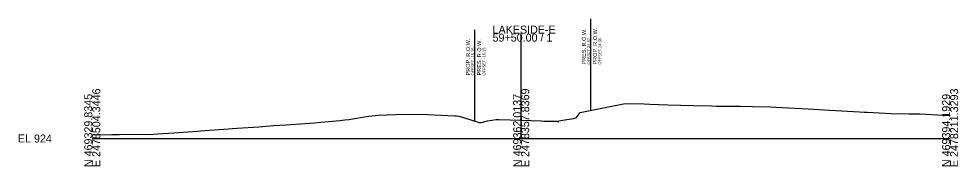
# Model space of a CAD drawing. Extents: x -26 to 2478923, y -10 to 469990.
# Drawn here: x -25.7 to 302.8, y 9990.3 to 10041.9 of the extents above; entities that cross this region are included whole.
import ezdxf

# ---------------------------------------------------------------- set-up
doc = ezdxf.new("R2010")
doc.units = 0
for name, color, linetype in [('DESIGN - ROW - Right-of-Way and Easement Labels', 7, 'Continuous'), ('DESIGN - ROW - Right-of-Way Linework', 7, 'Continuous'), ('DESIGN - SHEET - Light Grid', 7, 'Continuous'), ('SURVEY - GROUND - Top of Ground', 7, 'Continuous'), ('SURVEY - PROPERTY - ROW Lines', 7, 'Continuous'), ('SURVEY - PROPERTY - ROW Lines Text', 7, 'Continuous')]:
    doc.layers.add(name, color=color, linetype=linetype)

msp = doc.modelspace()

# ---------------------------------------------------------------- linework, layer by layer
at = {"layer": 'DESIGN - ROW - Right-of-Way Linework'}
for p, q in [((174.36, 10009.86), (174.36, 10041.86)), ((133.85, 10006.05), (133.85, 10038.05))]:
    msp.add_line(p, q, dxfattribs=at)
at = {"layer": 'DESIGN - SHEET - Light Grid'}
for p, q in [((150, 10000), (150, 10036.68)), ((0, 10000), (150, 10000)), ((150, 10000), (300, 10000))]:
    msp.add_line(p, q, dxfattribs=at)
at = {"layer": 'SURVEY - GROUND - Top of Ground'}
msp.add_lwpolyline([(0, 10001.32), (6.85, 10001.39), (9.58, 10001.4), (15.41, 10001.49), (19.85, 10001.43), (22.87, 10001.61), (28.58, 10001.93), (36.78, 10002.58), (37.8, 10002.67), (47.67, 10003.42), (48.91, 10003.53), (50.72, 10003.67), (58.29, 10004.06), (63.43, 10004.52), (67.82, 10004.76), (74.45, 10005.28), (77.75, 10005.49), (79.88, 10005.69), (86.74, 10006.31), (88.29, 10006.49), (89.73, 10006.67), (96.58, 10007.82), (100.11, 10008.13), (106.13, 10008.38), (110.39, 10008.49), (117.26, 10008.34), (126.82, 10007.97), (127.35, 10007.9), (128.29, 10007.77), (134.62, 10005.81), (135.22, 10005.62), (136.04, 10005.6), (138.25, 10006.23), (141.2, 10006.68), (142.16, 10006.64), (150, 10006.37), (157.03, 10006.12), (158.05, 10006.03), (158.69, 10006.11), (159.2, 10006.03), (160.23, 10006.04), (162.61, 10006.02), (163.11, 10005.86), (163.18, 10006.18), (165.94, 10006.67), (168.45, 10007.05), (169.21, 10007.23), (170.62, 10009.14), (175.31, 10010.05), (185.74, 10012.1), (186.73, 10012.23), (193.05, 10012.14), (194.94, 10012.06), (201.25, 10011.8), (205.8, 10011.65), (210.28, 10011.56), (216.51, 10011.39), (218.31, 10011.36), (225.77, 10011.27), (226.58, 10011.26), (230.93, 10011.18), (237.21, 10011.07), (239.1, 10011.01), (245.74, 10010.59), (250.4, 10010.32), (257.95, 10009.92), (268.37, 10009.33), (270.06, 10009.2), (271.03, 10009.15), (275.17, 10008.97), (279.35, 10008.79), (285.56, 10008.67), (287.68, 10008.59), (289.55, 10008.58), (297.57, 10008.16), (300, 10007.99)], dxfattribs=at)
at = {"layer": 'SURVEY - PROPERTY - ROW Lines'}
for p, q in [((174.37, 10031.86), (174.37, 10041.86)), ((133.85, 10028.05), (133.85, 10038.05)), ((174.37, 10020.86), (174.37, 10030.86)), ((133.85, 10017.05), (133.85, 10027.05)), ((174.37, 10009.86), (174.37, 10019.86)), ((133.85, 10006.05), (133.85, 10016.05))]:
    msp.add_line(p, q, dxfattribs=at)

# ---------------------------------------------------------------- texts
at = {"layer": 'DESIGN - ROW - Right-of-Way and Easement Labels'}
for s, height, p in [('PROP. R.O.W.', 1.4, (176.51, 10025.86)), ('PROP. R.O.W.', 1.4, (132.1, 10022.05)), ('OFFSET 24.36', 1, (178.01, 10025.86)), ('OFFSET -16.15', 1, (133.6, 10022.05))]:
    msp.add_text(s, height=height, rotation=90, dxfattribs=at).set_placement(p)
at = {"layer": 'DESIGN - SHEET - Light Grid'}
for s, p in [('59+50.00 / 1', (140, 10033.88)), ('LAKESIDE-E', (140, 10036.68)), ('EL 924', (-26, 9998.6))]:
    msp.add_text(s, height=2.8, dxfattribs=at).set_placement(p)
for s, p in [('E 2478504.3446', (2.8, 9990)), ('E 2478357.8369', (152.8, 9990)), ('E 2478211.3293', (302.8, 9990)), ('N 469329.8345', (0, 9990)), ('N 469362.0137', (150, 9990)), ('N 469394.1929', (300, 9990))]:
    msp.add_text(s, height=2.8, rotation=90, dxfattribs=at).set_placement(p)
at = {"layer": 'SURVEY - PROPERTY - ROW Lines Text'}
for s, height, p in [('PRES. R.O.W.', 1.4, (172.62, 10025.86)), ('PRES. R.O.W.', 1.4, (136, 10022.05)), ('OFFSET 24.37', 1, (174.12, 10025.86)), ('OFFSET -16.15', 1, (137.5, 10022.05))]:
    msp.add_text(s, height=height, rotation=90, dxfattribs=at).set_placement(p)

doc.saveas('drawing.dxf')
